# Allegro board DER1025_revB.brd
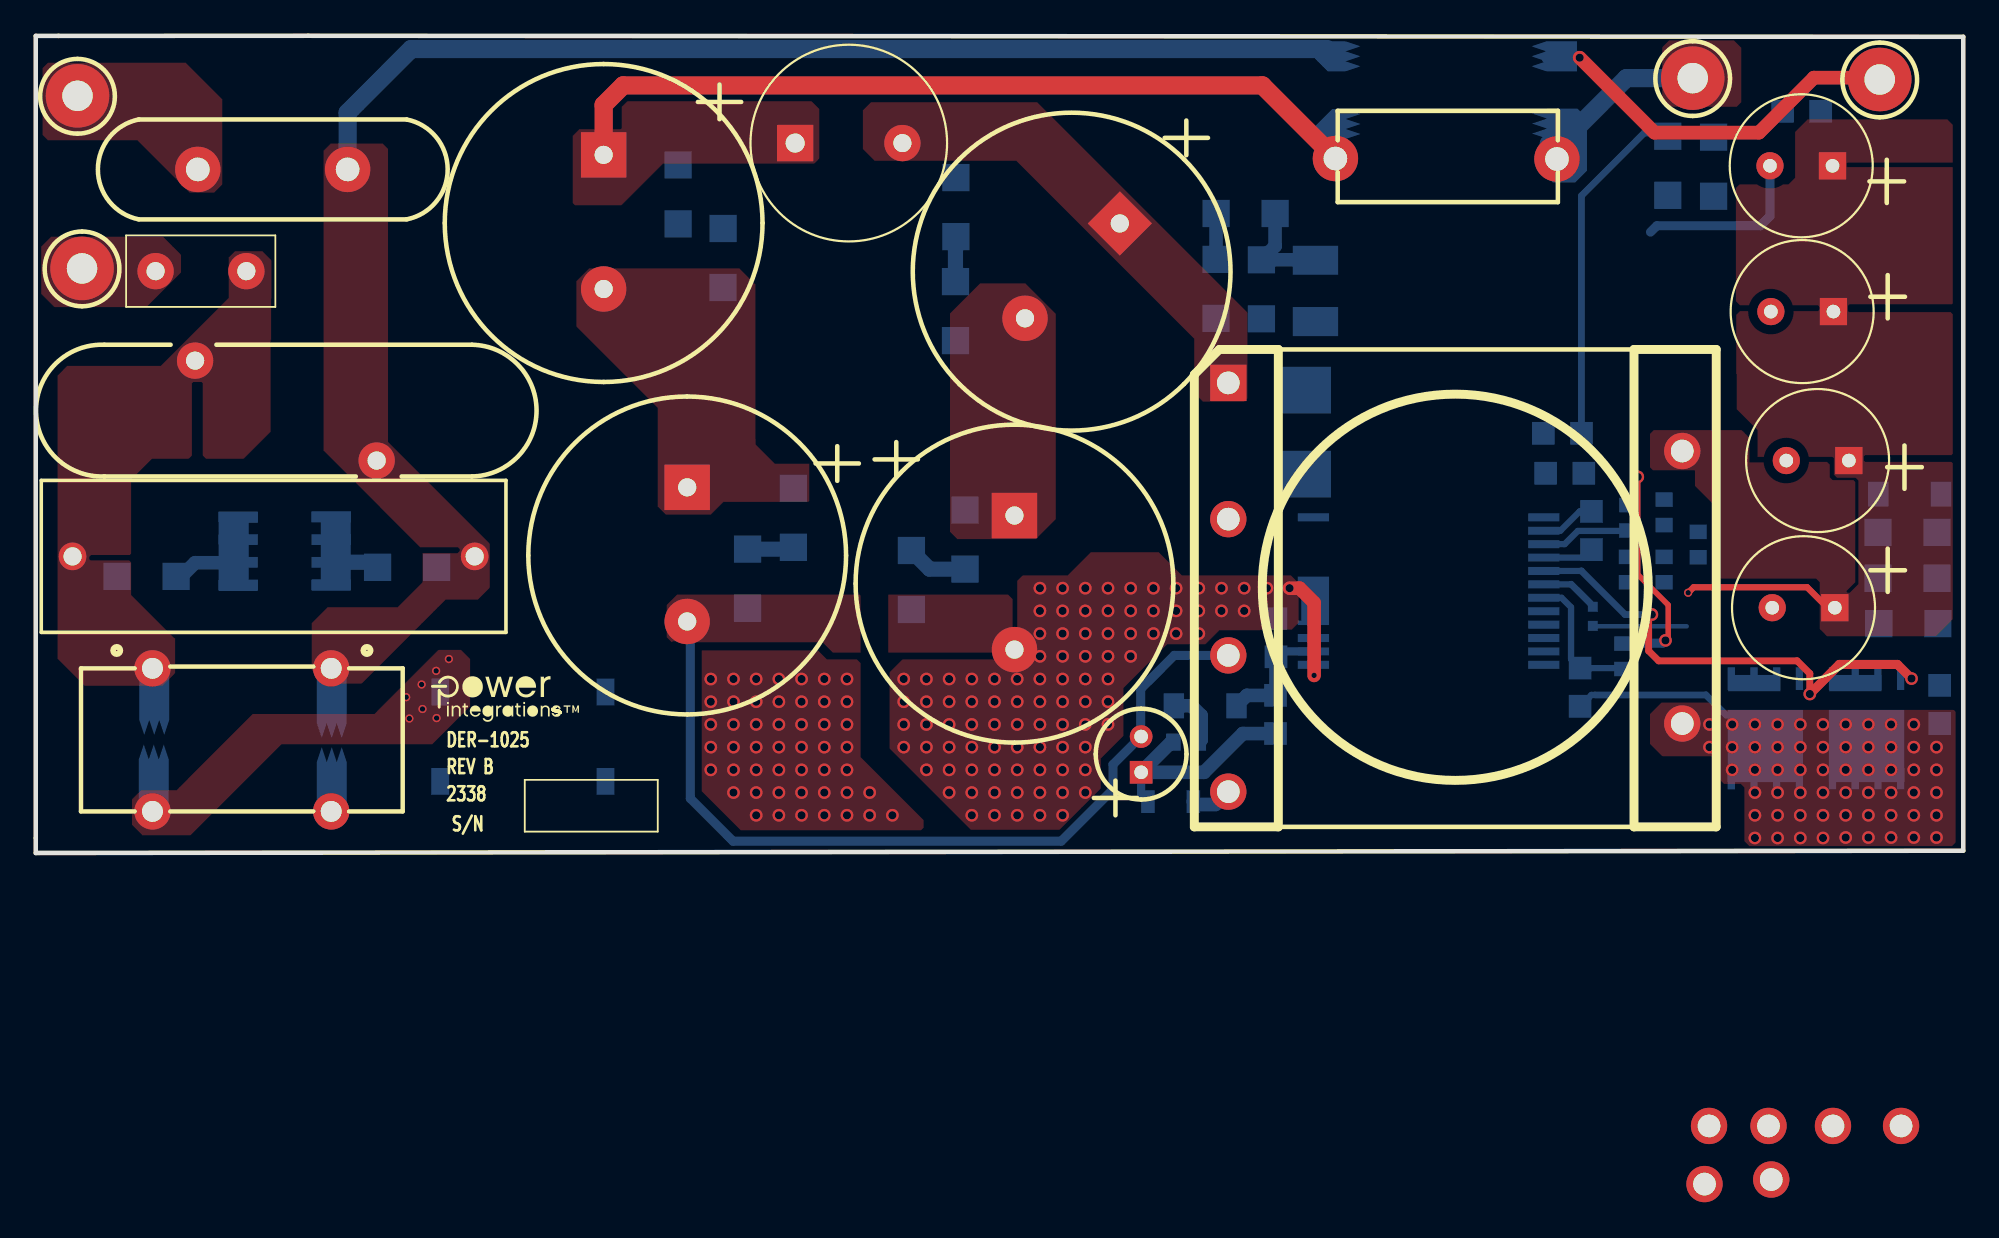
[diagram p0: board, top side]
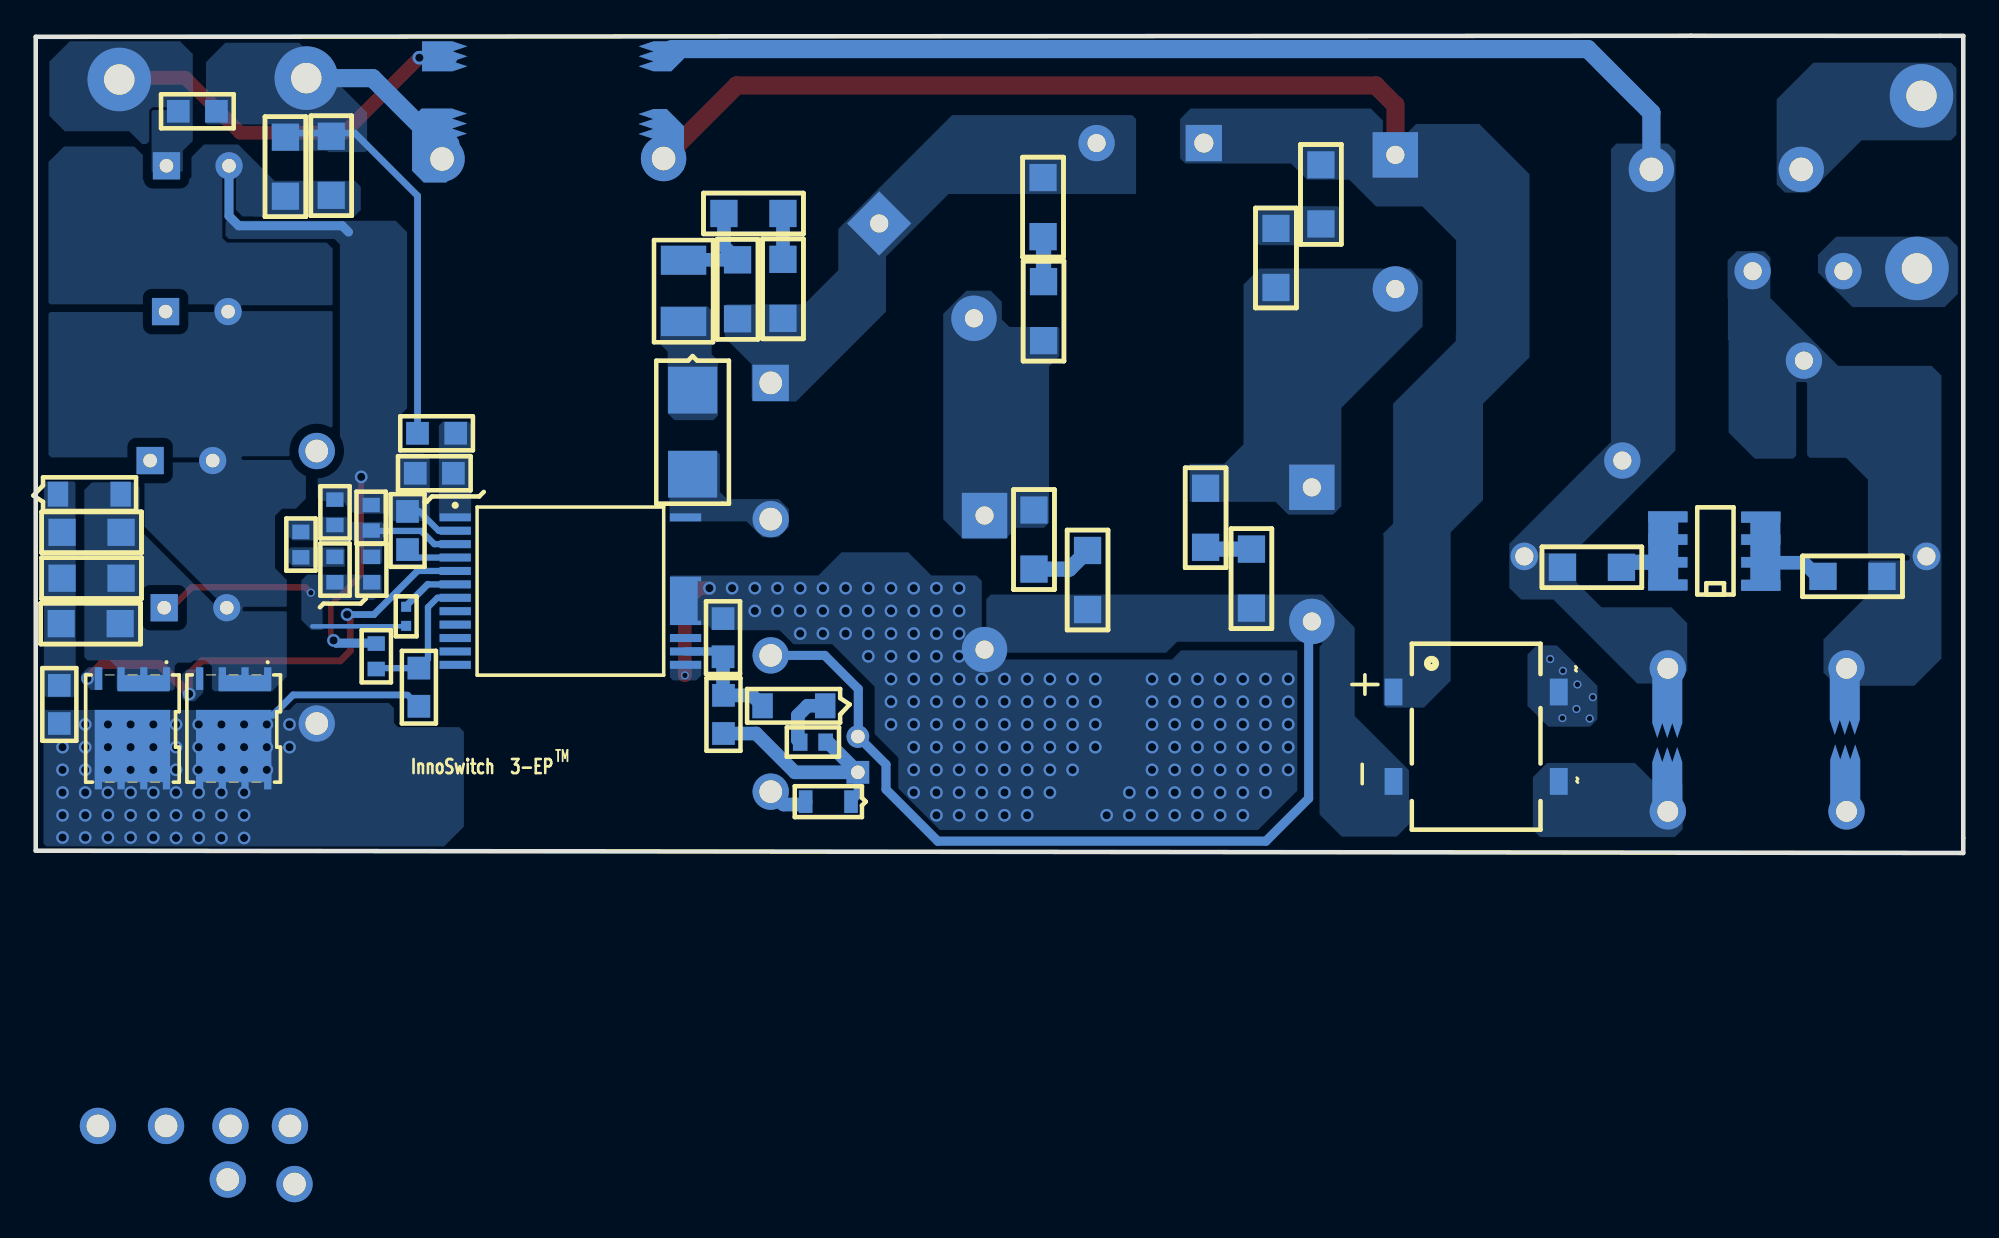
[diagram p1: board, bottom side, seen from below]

Outline 107.85 x 45.7 mm; copper layers: TOP, BOTTOM. Coordinates in mm from the lower left corner of the outline.
Outline path: 0,45.69 0,0 107.85,0.13 107.85,45.64 15.24,45.7 1.27,45.69 0,45.69

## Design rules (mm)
constraint set DEFAULT: min track width 0.203

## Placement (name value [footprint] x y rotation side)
BR1  RTBS60M  [PISMD_RTBS60M]  27.25 6.5 90 bottom
C1  220 uf  [PIPOLCAPCLYD710LS300040]  31.78 39.04 270 top
C2  220 uf  [PIPOLCAPCLYD710LS300040]  36.45 20.45 270 top
C3  220 uf  [PIPOLCAPCLYD710LS300040]  60.66 35.2 225 top
C4  220 uf  [PIPOLCAPCLYD710LS300040]  54.76 18.87 270 top
C5  1 nF  [PISMC1206]  68.58 29.87 90 bottom
C6  22 uF  [PIPOLCAPCLYD5MMD030]  61.85 5.51 90 top
C7  4.7 uF  [PISMC0805]  69.39 10.97 90 bottom
C8  3.3 nF  [PISMC0805]  106.53 7.24 90 bottom
C9  2.2 uF  [PISMC0805]  87.05 19.1 270 bottom
C10  330 pF  [PISMC0603]  88.8 10.29 90 bottom
C11  4.7 uF  [PISMC0805]  86.61 21.23 180 bottom
C12  330 pF  [PISMC0603]  89.08 19.46 270 bottom
C13  10 nF  [PISMC0603]  93.01 16.54 90 bottom
C14  680 uF  [PIPOLCAPCYLD8MMD030]  100.66 13.72 180 top
C15  680 uF  [PIPOLCAPCYLD8MMD030]  101.45 21.95 180 top
C16  680 uF  [PIPOLCAPCYLD8MMD030]  100.58 30.28 180 top
C17  680 uF  [PIPOLCAPCYLD8MMD030]  100.53 38.43 180 top
C18  2.2 uF  [PISMC0805]  99.87 41.48 180 bottom
CX1  220n  [PINPCAPRAD26X8P5X18D040]  13.31 16.59 0 top
CY1  2.2 nF  [PI_NP475X200LS395D040]  73.99 38.96 0 top
D1  S2T-CT  [PISMDO214AA12]  71.09 25.88 270 bottom
D2  BAV21WS-7-F  [PISMSOD323]  62.23 2.87 0 bottom
D3  UFM13PL-TP  [PI_SM_SOD-123_12]  106.6 20.07 180 bottom
F1  5 A  [PI_RST_MICROFUSE]  6.71 32.54 0 top
L  WHT  [PITPKEYSTONE125X125]  2.59 32.69 0 top
L1  2.5 mH  [PI4P18X8MMD046_12_43]  11.53 6.32 0 top
L4  12 uH  [PI_CHOKE_COILCRAFT_RFB1010]  45.49 39.7 0 top
N  BLK  [PITPKEYSTONE125X125]  2.34 42.34 0 top
NOREF  -  []  21.56 9.8 0 top
NOREF#2  -  []  0.05 45.67 0 top
NOREF#3  -  []  107.9 -229.89 0 top
NOREF#4  -  []  0.03 0 90 top
NOREF#5  -  []  -311.94 -305.49 0 top
Q1  SRT15N110L  [PISMPQFN5X6B]  94.87 9.75 0 bottom
Q2  SRT15N110L  [PISMPQFN5X6B]  100.53 9.75 0 bottom
R1  56.2 k  [PISMR1206]  4.55 15.47 0 bottom
R2  56.2 k  [PISMR1206]  19.13 15.98 0 bottom
R3  10 M  [PISMR1206]  35.94 38.48 270 bottom
R4  10 M  [PISMR1206]  38.46 34.92 270 bottom
R5  10 M  [PISMR1206]  42.39 20.4 270 bottom
R6  10 M  [PISMR1206]  39.83 16.99 270 bottom
R7  10 M  [PISMR1206]  51.49 37.77 270 bottom
R8  10 M  [PISMR1206]  51.46 31.95 270 bottom
R9  10 M  [PISMR1206]  51.99 19.18 270 bottom
R10  10 M  [PISMR1206]  49 16.92 270 bottom
R11  560 k  [PISMR1206]  66.04 29.9 90 bottom
R12  560 k  [PISMR1206]  66.04 35.76 0 bottom
R13  20  [PISMR1210]  71.6 33.15 270 bottom
R14  10  [PISMR0603]  63.65 6.2 0 bottom
R15  7.32 k  [PISMR0805]  69.37 6.68 90 bottom
R16  47.0  [PISMR0805]  86.41 8.2 90 bottom
R17  12  [PISMR1206]  106.38 15.37 180 bottom
R18  12  [PISMR1206]  106.43 12.83 180 bottom
R19  12  [PISMR1206]  106.38 17.93 180 bottom
R20  10  [PISMR0402]  87.12 12.7 90 bottom
R21  102 k  [PISMR0603]  89.05 15.14 90 bottom
R22  11.8 k  [PISMR0603]  91.11 18.34 90 bottom
R23  15 k  [PISMR0603]  91.11 15.14 90 bottom
R24  0.013 Ohms  [PISMR1206]  91.31 36.78 90 bottom
R25  0.013 Ohms  [PISMR1206]  93.88 36.73 90 bottom
R32  10  [PISMR0805]  86.49 23.47 180 bottom
RT1  5  [PI_RAD770X220LS330D052]  17.45 38.23 180 top
RTN  BLK  [PITPKEYSTONE125X125]  92.71 43.33 0 top
RV1  820V  [PI_DISC1100X290LS400X220D040]  8.92 27.53 0 top
T1  PQ26/20  [PI_BOBBIN_BPQ26_20_12P_2]  79.43 14.86 0 top
U1  CAP200DG  [PI_IC_SMD_SO8_CAPZERO]  11.33 14.99 90 bottom
U2  INN3699C-H606  [PI_IC_INSOP_24D]  84.38 18.77 180 bottom
VO  RED  [PITPKEYSTONE125X125]  103.17 43.26 0 top
VR1  MMSZ5247BT1G  [PI_SM_SOD-123_12]  63.68 8.23 0 bottom

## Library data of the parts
BR1 = DIODE BRIDGE_+-~~
C1-C4 = CAP POL: alternate symbols: (pi_cap_cly_d710_ls300_040_1000h,pipolcapd710ls3000401600lhoriz)
C5 C7 C9 C11 C12 CY1 = CAP NP
C6 = CAP POL: alternate symbols: (pipolcapclyd5x11mmd030H)
C8 C18 = CAP NP: alternate symbols: (Unisem_RMCF0805UL)
C10 C13 = CAP NP: alternate symbols: (Unisem_RMCF0603UL)
C14-C17 = CAP POL: alternate symbols: (pipolcapcyld8x16mmd030H)
CX1 = CAP NP: alternate symbols: (pinpcaprad26x8p5x18d040H)
D1-D3 = DIODE
F1 = FUSE: alternate symbols: (pirstmicrofusehoz)
L = TESTPOINT: alternate symbols: (TP_5010-14)
L1 = TORRID 4P_12_43a
L4 = INDUCTOR
N RTN VO = TESTPOINT
Q1 Q2 = FET_N_SGD_123_4_5678
R1-R14 R16-R19 R24 R25 R32 = R
R15 = R: alternate symbols: (Unisem_RMCF0805UL)
R20 = R: alternate symbols: (Unisem_RMCF0402UL,pismr0402_1)
R21-R23 = R: alternate symbols: (Unisem_RMCF0603UL)
RT1 = THERMISTOR
RV1 = VARISTOR
T1 = BPQ26/20_12P/GENERIC
U1 = CAPZero
U2 = Inno3EP_P15
VR1 = DIODE_ZENER

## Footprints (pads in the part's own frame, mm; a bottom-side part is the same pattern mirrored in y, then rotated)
PI4P18X8MMD046_12_43
  round 2.032 hole 1.168: 1(-5,4) 2(-5,-4) 3(5,-4) 4(5,4)
PI_BOBBIN_BPQ26_20_12P_2
  rect 2.032x2.032 hole 1.27: 1(-12.7,11.43)
  round 2.032 hole 1.27: 2(13.945,-33.376) 3(-12.7,3.81) 4(-12.7,-3.81) 5(17.678,-33.122) 6(-12.7,-11.43) 7(17.526,-30.124) 8(12.7,-7.62) 9(21.133,-30.124) 10(14.199,-30.124) 11(12.7,7.62) 12(24.943,-30.124)
PI_CHOKE_COILCRAFT_RFB1010
  rect 2.032x2.032 hole 1.067: 1(-3,0)
  round 2.032 hole 1.016: 2(3,0)
PI_DISC1100X290LS400X220D040
  round 2.032 hole 1.016: 1(0,0) 2(10.16,-5.588)
PI_IC_INSOP_24D
  rect 1.75x0.45 smd: 1(0,0) 2(0,-0.75) 3(0,-1.5) 4(0,-2.25) 5(0,-3) 6(0,-3.75) 7(0,-4.5) 8(0,-5.25) 9(0,-6) 10(0,-6.75) 11(0,-7.5) 12(0,-8.25) 13(12.89,-8.25) 14(12.89,-7.5) 15(12.89,-6.75) 24(12.89,0)
  custom 0.438x0.438 smd: 16(12.89,-4.67)
PI_IC_SMD_SO8_CAPZERO
  rect 0.599x2.2 smd: 1(0,0) 2(1.27,0) 3(2.54,0) 4(3.81,0) 5(3.81,5.199) 6(2.54,5.199) 7(1.27,5.199) 8(0,5.199)
PI_NP475X200LS395D040
  round 2.54 hole 1.321: 1(-1.27,-0.127) 2(11.125,-0.152)
PI_RAD770X220LS330D052
  round 2.54 hole 1.321: 1(0,0) 2(8.382,0)
PI_RST_MICROFUSE
  round 2.032 hole 1.016: 1(0,0) 2(5.08,0)
PI_SM_SOD-123_12
  rect 1.143x1.397 smd: 1(0,0) 2(3.505,0)
PINPCAPRAD26X8P5X18D040
  round 1.549 hole 1.016: 1(-11.25,0) 2(11.25,0)
PIPOLCAPCLYD5MMD030
  rect 1.27x1.27 hole 0.762: 1(-1,0)
  round 1.27 hole 0.762: 2(1,0)
PIPOLCAPCLYD710LS300040
  rect 2.54x2.54 hole 1.016: 1(0,0)
  round 2.54 hole 1.016: 2(7.5,0)
PIPOLCAPCYLD8MMD030
  rect 1.524x1.524 hole 0.762: 1(0,0)
  round 1.524 hole 0.762: 2(3.5,0)
PISMC0603
  rect 0.813x0.965 smd: 1(0,0) 2(1.422,0)
PISMC0805
  rect 1.27x1.27 smd: 1(0,0) 2(2.134,0)
PISMC1206
  rect 1.524x1.524 smd: 1(0,0) 2(3.302,0)
PISMD_RTBS60M
  rect 1.5x1 smd: 1(2.5,4.625) 2(-2.5,4.625) 3(2.5,-4.625) 4(-2.5,-4.625)
PISMDO214AA12
  rect 2.616x2.743 smd: 1(0,0) 2(4.699,0)
PISMPQFN5X6B
  rect 0.406x1.27 smd: 1(0,0) 2(1.27,0) 3(2.54,0) 4(3.81,0)
  rect 0.406x1.219 smd: 5(3.81,5.588) 6(2.54,5.588) 7(1.27,5.588) 8(0,5.588)
PISMR0402
  rect 0.559x0.559 smd: 1(0,0) 2(1.067,0)
PISMR0603
  rect 0.813x0.965 smd: 1(0,0) 2(1.422,0)
PISMR0805
  rect 1.27x1.27 smd: 1(0,0) 2(2.134,0)
PISMR1206
  rect 1.524x1.524 smd: 1(0,0) 2(3.302,0)
PISMR1210
  rect 1.626x2.54 smd: 1(0,0) 2(3.429,0)
PISMSOD323
  rect 0.762x1.27 smd: 1(0,0) 2(2.54,0)
PITPKEYSTONE125X125
  round 3.556 hole 1.702: 1(0,0)

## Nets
GND: BR1.2 C2.2 C4.2 C6.2 C7.2 R6.2 R10.2 T1.4 U2.13(VPIN) U2.16
GND SIGNAL: C18.2 CY1.2 R24.2 R25.2 R32.1 RTN.1
NC8: U2.8
NC9: U2.9
NC10: U2.10
NC11: U2.11
NC12: U2.12
RTN: C11.2 R32.2 U2.1
VO: C14.1 C15.1 C16.1 C17.1 C18.1 R20.1 R21.1 R23.1 T1.11 VO.1
N37461: C8.2 D3.1 R17.1 R18.1 R19.1
N37469: C9.1 C10.2 C11.1 C12.1 C14.2 C15.2 C16.2 C17.2 D3.2 Q1.1 Q1.2 Q1.3(S3) Q2.1 Q2.2 Q2.3(S3) R17.2 R18.2 R19.2 R22.2 R24.1 R25.1 U2.2
N38055: C6.1 D2.1 R14.1 R15.1
N38189: C7.1 R15.2 U2.14 VR1.2
N100542: D1.1 R13.2
N100730: C5.2 R12.2 R13.1
N100745: C3.1 C5.1 L4.2 R7.1 R11.1 T1.1
N100844: R11.2 R12.1
N104424: C8.1 Q1.5 Q1.6 Q1.7 Q1.8 Q2.5 Q2.6 Q2.7 Q2.8 R16.1 T1.8
N108780: C12.2 C13.2 R21.2 R22.1 U2.3
N109833: C13.1 R23.2
N12293127: C10.1 R16.2 U2.7
N12298409: D1.2 T1.3 U2.24
N12305547: Q1.4 Q2.4 U2.5
N12325575: C9.2 U2.4
N12352620: C3.2 C4.1 R8.2 R9.1
N12353333: BR1.1 C1.1 CY1.1 L4.1 R3.1
N12359836: R7.2 R8.1
N12360252: R9.2 R10.1
N12374653: R3.2 R4.1
N12374691: C1.2 C2.1 R4.2 R5.1
N12374751: R5.2 R6.1
N12405316: BR1.3 L1.2
N12405324: BR1.4 L1.3
N12405376: CX1.1 F1.2 L1.1 R1.1 RV1.1
N12405380: CX1.2 L1.4 R2.2 RT1.1 RV1.2
N12407233: F1.1 L.1
N12407237: N.1 RT1.2
N12426226: R20.2 U2.6
N12433775: D2.2 T1.6
N12606053: R14.2 VR1.1
N13222962: R1.2 U1.2
N13223037: R2.1 U1.7

Pads without a net: T1 2 5 7 9 10 12; U1 1 3 4 5 6 8; U2 15

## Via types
v1: diameter 0.711, hole 0.457, TOP to BOTTOM, 207 vias
v2: diameter 0.457, hole 0.305, TOP to BOTTOM, 9 vias

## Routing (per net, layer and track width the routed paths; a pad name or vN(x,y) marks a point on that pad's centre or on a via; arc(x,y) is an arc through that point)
GND: length 53.1
  TOP w0.762: v1(70.15,14.81) 70.71,14.81 71.53,14 v2(71.53,9.93)
  BOTTOM w0.457: C6.2 61.84,6.51 61.82,6.5
  BOTTOM w0.508: T1.4 63.7,11.05 61.82,9.17 61.82,6.51 ; 36.63,12.57 36.63,3.05 39.01,0.66 57.38,0.66 60.27,3.56 60.27,4.95 61.82,6.5 61.82,6.51 ; 61.82,6.51 61.85,6.49
  vias: v1(37.77,9.73) v1(37.77,8.46) v1(37.77,7.19) v1(37.77,5.92) v1(37.77,4.65) v1(39.04,9.73) v1(39.04,8.46) v1(39.04,7.19) v1(39.04,5.92) v1(39.04,4.65) v1(39.04,3.38) v1(40.31,9.73) v1(40.31,8.46) v1(40.31,7.19) v1(40.31,5.92) v1(40.31,4.65) v1(40.31,3.38) v1(40.31,2.11) v1(41.58,9.73) v1(41.58,8.46) v1(41.58,7.19) v1(41.58,5.92) v1(41.58,4.65) v1(41.58,3.38) v1(41.58,2.11) v1(42.85,9.73) v1(42.85,8.46) v1(42.85,7.19) v1(42.85,5.92) v1(42.85,4.65) v1(42.85,3.38) v1(42.85,2.11) v1(44.12,9.73) v1(44.12,8.46) v1(44.12,7.19) v1(44.12,5.92) v1(44.12,4.65) v1(44.12,3.38) v1(44.12,2.11) v1(45.39,9.73) v1(45.39,8.46) v1(45.39,7.19) v1(45.39,5.92) v1(45.39,4.65) v1(45.39,3.38) v1(45.39,2.11) v1(46.66,3.38) v1(46.66,2.11) v1(47.93,2.11) v1(48.56,9.73) v1(48.56,8.46) v1(48.56,7.19) v1(48.56,5.92) v1(49.83,9.73) v1(49.83,8.46) v1(49.83,7.19) v1(49.83,5.92) v1(49.83,4.65) v1(51.1,9.73) v1(51.1,8.46) v1(51.1,7.19) v1(51.1,5.92) v1(51.1,4.65) v1(51.1,3.38) v1(52.37,9.73) v1(52.37,8.46) v1(52.37,7.19) v1(52.37,5.92) v1(52.37,4.65) v1(52.37,3.38) v1(52.37,2.11) v1(53.64,9.73) v1(53.64,8.46) v1(53.64,7.19) v1(53.64,5.92) v1(53.64,4.65) v1(53.64,3.38) v1(53.64,2.11) v1(54.91,9.73) v1(54.91,8.46) v1(54.91,7.19) v1(54.91,5.92) v1(54.91,4.65) v1(54.91,3.38) v1(54.91,2.11) v1(56.18,14.81) v1(56.18,13.54) v1(56.18,12.27) v1(56.18,11) v1(56.18,9.73) v1(56.18,8.46) v1(56.18,7.19) v1(56.18,5.92) v1(56.18,4.65) v1(56.18,3.38) v1(56.18,2.11) v1(57.45,14.81) v1(57.45,13.54) v1(57.45,12.27) v1(57.45,11) v1(57.45,9.73) v1(57.45,8.46) v1(57.45,7.19) v1(57.45,5.92) v1(57.45,4.65) v1(57.45,3.38) v1(57.45,2.11) v1(58.72,14.81) v1(58.72,13.54) v1(58.72,12.27) v1(58.72,11) v1(58.72,9.73) v1(58.72,8.46) v1(58.72,7.19) v1(58.72,5.92) v1(58.72,4.65) v1(58.72,3.38) v1(59.99,14.81) v1(59.99,13.54) v1(59.99,12.27) v1(59.99,11) v1(59.99,9.73) v1(59.99,8.46) v1(59.99,7.19) v1(61.26,14.81) v1(61.26,13.54) v1(61.26,12.27) v1(61.26,11) v1(62.53,14.81) v1(62.53,13.54) v1(62.53,12.27) v1(63.8,14.81) v1(63.8,13.54) v1(63.8,12.27) v1(65.07,14.81) v1(65.07,13.54) v1(65.07,12.27) v1(66.34,14.81) v1(66.34,13.54) v1(67.61,14.81) v1(67.61,13.54) v1(68.88,14.81)
GND SIGNAL: length 33
  BOTTOM w0.381: 93.29,40.26 89.99,40.26 86.49,36.75 R32.1
  BOTTOM w1.016: CY1.2 84.73,38.81 84.66,38.73 ; RTN.1 89,43.33 85.32,39.65 84.66,39.65 84.66,38.73 ; 84.66,38.73 84.66,38.28
VO: length 35.6
  TOP w0.35: C14.1 100.25,13.72 99.11,14.86 92.76,14.86 v2(92.46,14.55)
  TOP w0.762: v1(86.39,44.48) 90.58,40.28 96.42,40.28 99.49,43.36 103.05,43.36
  BOTTOM w0.254: 87.12,12.75 87.17,12.7 ; 92.37,12.67 87.2,12.67
  BOTTOM w0.35: R20.1 87.17,12.7 87.2,12.67
  BOTTOM w0.762: 84.63,44.48 v1(86.39,44.48)
N37469: length 25.4
  TOP w0.305: v1(89.64,21.03) 89.64,15.57 91.34,13.87 91.34,12.04 v1(91.19,11.89)
  BOTTOM w0.35: 88.82,11.73 C10.2 ; 86.44,19.1 86.39,19.1 85.31,18.02 U2.2
  BOTTOM w0.381: 87.07,19.1 C9.1 86.44,19.1
  BOTTOM w0.508: v1(91.19,11.89) 91.03,11.73 88.82,11.73 ; 90.35,34.72 90.7,35.08 96.49,35.08 97.03,35.62 C17.2
N38055: length 12.7
  BOTTOM w0.457: C6.1 61.85,3.25 D2.1
  BOTTOM w0.762: R15.1 67.54,6.68 65.37,4.51 C6.1 63.53,6.2 R14.1
N38189: length 6.8
  BOTTOM w0.457: U2.14 69.69,11.27 C7.1
  BOTTOM w0.762: VR1.2 67.77,8.81 R15.2 69.39,8.84 C7.1
N100730: length 5.9
  BOTTOM w0.762: R12.2 69.34,33.93 C5.2 71.58,33.17 R13.1
N100844: length 2.6
  BOTTOM w0.762: R12.1 R11.2
N104424: length 8.9
  BOTTOM w0.35: R16.1 87.05,8.84 87.25,8.84
  BOTTOM w0.381: 94.59,7.7 93.45,8.84 87.25,8.84
  vias: v1(93.65,7.19) v1(93.65,5.92) v1(94.92,7.19) v1(94.92,5.92) v1(94.92,4.65) v1(96.19,7.19) v1(96.19,5.92) v1(96.19,4.65) v1(96.19,3.38) v1(96.19,2.11) v1(96.19,0.84) v1(97.46,7.19) v1(97.46,5.92) v1(97.46,4.65) v1(97.46,3.38) v1(97.46,2.11) v1(97.46,0.84) v1(98.73,7.19) v1(98.73,5.92) v1(98.73,4.65) v1(98.73,3.38) v1(98.73,2.11) v1(98.73,0.84) v1(100,7.19) v1(100,5.92) v1(100,4.65) v1(100,3.38) v1(100,2.11) v1(100,0.84) v1(101.27,7.19) v1(101.27,5.92) v1(101.27,4.65) v1(101.27,3.38) v1(101.27,2.11) v1(101.27,0.86) v1(102.54,7.19) v1(102.54,5.92) v1(102.54,4.65) v1(102.54,3.38) v1(102.54,2.11) v1(102.54,0.86) v1(103.81,7.19) v1(103.81,5.92) v1(103.81,4.65) v1(103.81,3.38) v1(103.81,2.11) v1(103.81,0.86) v1(105.08,7.19) v1(105.08,5.92) v1(105.08,4.65) v1(105.08,3.38) v1(105.08,2.11) v1(105.08,0.86) v1(106.35,5.92) v1(106.35,4.65) v1(106.35,3.38) v1(106.35,2.11) v1(106.35,0.86)
N108780: length 5
  BOTTOM w0.35: C12.2 89.05,18.01 86.28,18.01 85.55,17.27 U2.3
N12293127: length 7.8
  BOTTOM w0.35: C10.1 88.75,10.34 R16.2 85.9,10.85 85.9,13.74 85.37,14.27 U2.7
N12298409: length 0.4
  BOTTOM w0.381: 71.5,21.16 71.12,21.16 D1.2 ; 66.77,18.77 66.78,18.78
N12305547: length 26.6
  TOP w0.381: v1(99.26,8.89) 99.26,10.03 98.55,10.74 90.81,10.74 90.25,11.3 90.25,13.16 v1(90.42,13.34)
  TOP w0.508: v1(104.95,9.75) 104.17,10.54 100.91,10.54 v1(99.26,8.89)
  BOTTOM w0.35: U2.5 86.47,15.77 86.48,15.78
  BOTTOM w0.381: 86.48,15.78 88.93,13.34 v1(90.42,13.34)
N12325575: length 2.9
  BOTTOM w0.35: C9.2 86.6,16.52 U2.4
  BOTTOM w0.381: 87.07,16.97 C9.2
N12353333: length 45.9
  TOP w1.016: CY1.1 68.63,42.93 32.87,42.93 31.78,41.83 C1.1
N12359836: length 2.5
  BOTTOM w0.85: R7.2 51.46,34.44 R8.1
N12360252: length 3.4
  BOTTOM w0.85: R9.2 50.01,15.88 49,16.89 R10.1
N12374751: length 2.6
  BOTTOM w0.85: R5.2 42.29,16.99 R6.1
N12405316:
  vias: v2(20.73,8.71) v2(20.9,7.52) v2(21.59,9.42) v2(21.64,8.05) v2(22.4,10.19) v2(22.43,7.54) v2(23.11,10.85)
N12405380: length 59.5
  BOTTOM w1.016: RT1.1 17.45,41.4 21.01,44.96 72.26,44.96
N12426226: length 3.3
  BOTTOM w0.35: 85.91,15.03 85.9,15.02 U2.6 ; 87.12,13.82 R20.2
  BOTTOM w0.381: 85.91,15.03 87.12,13.82
N12433775: length 2.3
  BOTTOM w0.762: D2.2 64.93,2.71 66.01,2.71 66.73,3.43
N12606053: length 3.3
  BOTTOM w0.762: R14.2 65.21,6.33 65.21,7.69 64.67,8.23 VR1.1
N13222962: length 3.8
  BOTTOM w0.762: U1.2 11.3,16.23 8.92,16.23 8.15,15.47 R1.2
N13223037: length 2.7
  BOTTOM w0.85: U1.7 18.85,16.26 R2.1

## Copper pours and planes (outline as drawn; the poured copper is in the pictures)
GND on TOP: 55.22,15.52 57.76,15.52 57.76,15.54 59.03,16.81 62.84,16.81 64.14,15.52 70.23,15.52 70.66,15.09 70.66,12.88 70.28,12.5 68.88,12.5 68.88,12.47 68.5,12.47 68.49,12.46 66.23,12.46 65.44,11.67 63.31,11.67 60.86,9.22 60.86,6.55 59.59,5.28 59.59,3.61 57.28,1.3 52.32,1.3 47.78,5.84 47.78,10.11 48.49,10.82 53.62,10.82 53.72,10.92 53.72,11.07 53.59,11.2 47.7,11.2 47.7,14.43 47.73,14.45 54.41,14.45 54.66,14.2 54.66,12.27 54.74,12.19 54.86,12.19 54.91,12.24 54.91,15.21
GND on TOP: 43.76,11.33 44.27,10.82 45.95,10.82 46.15,10.62 46.15,5.36 49.68,1.83 49.68,1.42 49.53,1.27 39.45,1.27 37.26,3.45 37.26,11.33
GND on TOP: 46.15,11.2 44.6,11.2 44.02,11.79 36.8,11.79 36.75,11.84 35.64,11.84 35.59,11.79 35.31,12.06 35.31,13.87 35.89,14.45 46.1,14.45 46.15,14.4
GND on BOTTOM: 55.22,15.52 57.73,15.52 59.03,16.81 62.76,16.81 64.06,15.52 72.34,15.52 72.34,12.8 72.29,12.75 70.26,12.75 69.98,12.47 68.5,12.47 68.49,12.46 66.23,12.46 65.44,11.67 63.28,11.67 60.91,9.3 60.91,6.65 59.59,5.33 59.59,3.61 57.26,1.28 39.46,1.28 37.26,3.48 37.26,11.33 43.76,11.33 44.27,10.82 53.62,10.82 53.72,10.92 53.72,11.07 53.59,11.2 44.6,11.2 43.99,11.81 35.94,11.81 35.86,11.73 35.86,11.68 36.02,11.53 36.02,2.16 34.77,0.91 31.7,0.91 31.01,1.6 31.01,4.62 34.05,7.66 34.05,12.61 35.26,13.82 35.26,13.84 35.86,14.45 54.41,14.45 54.66,14.2 54.66,12.27 54.74,12.19 54.86,12.19 54.91,12.24 54.91,15.21
GND on BOTTOM: 70.61,10.74 72.29,10.74 72.36,10.67 72.36,9.83 72.19,9.65 70.89,9.65 70.61,9.93
GND SIGNAL on BOTTOM (solid shape): 86.79,41.1 86.79,38.15 86.13,37.49 84.89,37.49 84.53,37.85 84.53,39.96 83.72,40.23 84.56,40.51 83.72,40.79 84.56,41.07 83.72,41.35 84.56,41.63 86.26,41.63
GND SIGNAL on TOP: 95.02,45.44 95.43,45.03 95.43,41.99 95.17,41.73 91.41,41.73 91.01,42.14 91.01,45.06 91.39,45.44
GND SIGNAL on BOTTOM: 98.25,40.74 98.32,40.82 98.32,44.22 97.23,45.31 93.12,45.31 91.92,44.12 91.92,44.02 89.31,41.4 89.31,39.29 89.41,39.19 91.47,39.19 91.54,39.27 94.11,39.27 94.11,40.13 94.72,40.74
RTN on BOTTOM: 85.29,18.59 85.29,23.9 85.06,24.13 83.67,24.13 83.49,23.95 83.49,18.57 83.52,18.54 85.24,18.54
VO on BOTTOM (solid shape): 86.23,43.71 84.53,43.71 83.69,43.99 84.53,44.27 83.69,44.55 84.53,44.83 83.69,45.11 84.53,45.39 86.23,45.39
VO on TOP: outline of 86 points within 90.32,12.12 107.26,41.02
VO on BOTTOM: 99.77,45.39 105.94,45.39 107.09,44.25 107.09,41.22 106.22,40.36 102.62,40.36 101.9,39.65 101.65,39.65 101.5,39.8 101.5,41.53 101.32,41.71 100.53,41.71 100.51,41.68 100.51,41.58 100.53,41.55 101.27,41.55 101.37,41.45 101.37,38.1 99.67,38.1 99.62,38.15 99.62,39.27 99.06,39.83 99.06,44.68
VO on BOTTOM: 88.57,15.57 92.66,15.57 92.99,15.24 92.99,13.03 92.43,12.47 91.8,12.47 91.8,13.72 91.36,14.15 88.85,14.15 88.49,14.5 88.49,15.49
N37461 on BOTTOM: 107.39,8.86 107.24,8.71 105.77,8.71 105.61,8.86 105.61,18.24 105.63,18.25 105.63,20.69 105.71,20.78 107.31,20.78 107.39,20.7
N37469 on BOTTOM (solid shape): 97.61,9.04 94.69,9.04 94.69,9.96 97.61,9.96
N37469 on BOTTOM (solid shape): 103.28,9.04 100.36,9.04 100.36,9.96 103.28,9.96
N37469 on BOTTOM: outline of 107 points within 89.66,9.04 107.14,39.62
N37469 on BOTTOM: 86.08,18.47 87.71,18.47 88.21,18.97 90.02,18.97 90.55,19.51 90.55,19.56 90.68,19.68 91.9,19.68 92.08,19.86 92.08,21.08 90.83,22.33 90.83,34.04 91.14,34.34 97.05,34.34 97.23,34.52 97.23,35.28 97.16,35.36 87.71,35.36 87.07,34.72 87.07,24.87 87.48,24.46 87.48,22.71 87.12,22.35 86.16,22.35 85.8,22 85.8,18.75
N100542 on BOTTOM: 70.28,30.58 72.85,30.58 72.91,30.52 72.91,28.46 72.49,28.04 72.49,24.59 72.11,24.21 69.93,24.21 69.67,24.46 69.67,27.53 70.03,27.89 70.03,30.33
N100745 on TOP: 67.79,30.23 67.79,25.43 67.61,25.25 65.3,25.25 64.82,25.73 64.82,28.75 54.86,38.71 46.94,38.71 46.28,39.37 46.28,41.53 46.71,41.96 46.71,41.99 56.03,41.99
N100745 on BOTTOM: 56.58,41.26 62.94,34.9 62.94,32.59 64.85,30.68 69.19,30.68 69.29,30.58 69.29,28.83 67.79,27.33 67.79,25.43 67.61,25.25 65.3,25.25 60.27,30.28 60.27,33.35 56.77,36.86 46.28,36.86 46.28,41.05 46.49,41.26
N104424 on BOTTOM (solid shape): 98.88,3.96 94.67,3.96 94.67,8 98.88,8
N104424 on BOTTOM (solid shape): 104.55,3.96 100.33,3.96 100.33,8 104.55,8
N104424 on TOP: 93.65,8.41 94.06,8 107.31,8 107.42,7.9 107.42,0.58 107.21,0.38 95.89,0.38 95.61,0.66 95.61,3.66 95.4,3.86 94.46,3.86 94.21,4.11 94.21,5.03 93.83,5.41 91.01,5.41 90.32,6.1 90.32,7.77 90.96,8.41
N104424 on BOTTOM: 107.31,8 107.42,7.9 107.42,0.53 107.25,0.37 85,0.37 83.9,1.47 83.9,6.78 84.15,7.04 87.58,7.04 87.81,7.26 87.81,8.1 88.09,8.38 93.27,8.38 93.65,8
N108780 on BOTTOM: 90.22,18.52 90.51,18.81 90.53,18.8 93.42,18.8 93.7,18.52 93.7,17.7 93.47,17.48 90.09,17.48 89.66,17.04 89.66,16.23 89.59,16.15 88.57,16.15 88.47,16.26 88.47,17.55 88.11,17.91 88.11,18.14 88.49,18.52
N109833 on BOTTOM: 93.57,17.09 90.65,17.09 90.55,16.99 90.55,16 93.45,16 93.68,16.23 93.68,16.99
N12298409 on BOTTOM: 72.39,18.54 68.07,18.54 67.18,17.65 66.29,17.65 65.71,18.24 65.71,19.23 66.27,19.79 69.16,19.79 69.57,20.19 69.57,22.3 69.72,22.45 72.39,22.45
N12305547 on BOTTOM: 104.14,10.39 104.9,10.39 105.31,9.98 105.31,9.65 104.78,9.12 104.09,9.12 104.09,10.34
N12305547 on BOTTOM: 98.48,10.41 99.24,10.41 99.67,9.98 99.67,8.66 99.49,8.48 98.96,8.48 98.48,8.97
N12352620 on TOP: 57.07,30.15 57.07,18.67 55.96,17.55 51.56,17.55 51.16,17.96 51.16,30.18 52.83,31.85 55.37,31.85
N12352620 on BOTTOM: 57.07,30.15 57.07,18.67 55.96,17.55 53.52,17.55 53.52,17.63 52.96,18.19 51.43,18.19 51.16,18.47 51.16,27.2 50.57,27.79 50.57,29.34 50.65,29.41 53.37,29.41 53.8,29.84 53.8,30.84 54.41,31.45 55.78,31.45
N12353333 on BOTTOM (solid shape): 74.12,41.33 73.28,41.05 74.12,40.77 73.28,40.49 74.12,40.21 73.28,39.93 73.28,38.28 72.87,37.87 71.96,37.87 71.58,38.25 71.58,40.64 72.54,41.61 73.28,41.61
N12353333 on TOP: 35.1,38.56 32.77,36.22 30.18,36.22 30.05,36.35 30.05,40.11 30.42,40.47 32.73,40.47 32.79,40.54 32.79,41.73 33.1,42.04 43.41,42.04 43.84,41.61 43.84,38.84 43.56,38.56
N12353333 on BOTTOM: 26.87,19.74 26.87,25.12 24.27,27.72 24.27,37.96 27.08,40.77 30.61,40.77 31.04,40.34 31.04,38.48 31.29,38.23 32.31,38.23 32.47,38.39 32.47,40.96 33.15,41.63 43.23,41.63 43.81,41.05 43.81,38.84 43.54,38.56 37.62,38.56 36.72,37.66 34.35,37.66 32.85,36.16 30.26,36.16 28.37,34.26 28.37,29.01 28.4,28.98 28.4,28.63 31.9,25.12 31.9,18.41 32.49,17.83 32.44,17.78 32.44,8.31 32.26,8.13 30.18,8.13 28.68,9.63 28.68,17.93
N12374653 on BOTTOM: 35,36.17 39.29,36.17 39.65,35.81 39.65,34.26 39.37,33.99 35.05,33.99 34.8,34.24 34.8,35.97
N12374691 on TOP, BOTTOM: 40.27,23.14 40.28,23.13 40.28,22.84 41.35,21.77 43.28,21.77 43.28,19.68 43.23,19.63 38.48,19.63 37.77,18.92 35.26,18.92 34.8,19.38 34.8,24.89 30.25,29.44 30.25,31.98 30.96,32.69 39.37,32.69 40.27,31.79
N12405316 on BOTTOM (solid shape): 7.44,5.23 7.44,2.18 5.77,2.18 5.77,5.23 6.05,6.07 6.32,5.23 6.6,6.07 6.88,5.23 7.16,6.07
N12405316 on TOP: 13.75,6.08 22.19,6.08 24.31,8.2 24.31,10.85 23.8,11.35 22.53,11.35 18.95,7.77 12.14,7.77 7.87,3.51 5.89,3.51 5.38,3 5.38,1.57 5.99,0.97 6.02,0.99 8.66,0.99
N12405316 on BOTTOM: 22.73,11.61 23.88,11.61 24.38,11.1 24.38,8.23 23.22,7.06 20.88,7.06 20.47,7.47 20.47,9.35
N12405324 on BOTTOM (solid shape): 17.4,5.08 17.4,2.06 15.72,2.06 15.72,5.08 16,5.92 16.28,5.08 16.56,5.92 16.84,5.08 17.12,5.92
N12405324 on BOTTOM: 18.36,5.03 17.17,3.84 15.67,3.84 15.7,3.81 15.7,1.32 16.13,0.89 23.67,0.89 24.08,1.3 24.08,4.24 23.29,5.03
N12405376 on BOTTOM (solid shape): 7.47,7.44 7.19,6.6 6.91,7.44 6.63,6.6 6.35,7.44 6.07,6.6 5.79,7.44 5.79,10.26 7.47,10.26
N12405376 on TOP: 11.15,33.66 12.67,33.66 13.18,33.15 13.18,31.01 13.17,31 13.17,28.71 13.14,28.69 13.14,23.56 11.63,22.05 9.52,22.05 9.35,22.23 9.35,26.26 9.27,26.34 8.81,26.34 8.74,26.26 8.74,22.23 8.56,22.05 6.5,22.05 5.33,20.88 5.33,16.74 5.26,16.66 3.1,16.66 3,16.56 3,16.43 3.07,16.36 5.23,16.36 5.33,16.26 5.33,14.43 7.75,12.01 7.8,12.01 7.8,10.06 7.09,9.35 2.74,9.35 1.22,10.87 1.22,26.7 1.77,27.24 7,27.24 10.79,31.04 10.79,33.3
N12405376 on BOTTOM: 11.15,33.66 12.67,33.66 13.18,33.15 13.18,31.01 13.17,31 13.17,28.71 13.13,28.68 13.13,23.52 11.66,22.05 9.52,22.05 9.35,22.23 9.35,26.29 9.3,26.34 8.81,26.34 8.74,26.26 8.74,22.25 8.59,22.1 6.55,22.1 5.33,20.88 5.33,16.74 5.26,16.66 3.1,16.66 3,16.56 3,16.43 3.07,16.36 5.23,16.36 5.33,16.26 5.33,14.43 7.77,11.99 7.82,11.99 7.82,10.08 7.09,9.35 2.74,9.35 1.22,10.87 1.22,26.7 1.77,27.24 7,27.24 10.79,31.04 10.79,33.3
N12405380 on BOTTOM (solid shape): 17.4,7.26 17.12,6.43 16.84,7.26 16.56,6.43 16.28,7.26 16,6.43 15.72,7.26 15.72,10.36 17.4,10.36
N12405380 on BOTTOM (solid shape): 74.12,45.11 73.28,44.83 74.12,44.55 73.28,44.27 74.12,43.99 73.28,43.71 72.29,43.71 71.58,44.42 71.58,45.39 73.28,45.39
N12405380 on TOP: 16.51,39.67 19.41,39.67 19.71,39.37 19.71,22.99 25.4,17.3 25.4,14.83 24.74,14.17 22.94,14.17 18.24,9.47 16.21,9.47 15.44,10.24 15.44,12.85 16.33,13.74 20.24,13.74 21.64,15.14 21.64,16.76 23.6,16.76 23.72,16.89 23.72,16.99 23.62,17.09 21.51,17.09 16.1,22.5 16.1,39.27
N12405380 on BOTTOM: 16.51,39.67 19.41,39.67 19.71,39.37 19.71,22.99 25.4,17.3 25.4,14.83 24.74,14.17 22.94,14.17 18.24,9.47 16.15,9.47 15.44,10.19 15.44,12.85 16.33,13.74 20.24,13.74 21.64,15.14 21.64,16.76 23.6,16.76 23.72,16.89 23.72,16.99 23.62,17.09 21.51,17.09 16.1,22.5 16.1,39.27
N12407233 on TOP, BOTTOM: 0.86,34.47 7.11,34.47 8.13,33.45 8.13,32.46 6.2,30.53 1.04,30.53 0.3,31.27 0.3,33.91
N12407237 on TOP, BOTTOM: 0.69,44.2 8.38,44.2 10.44,42.14 10.44,37.39 9.98,36.93 8.61,36.93 5.69,39.85 0.69,39.85 0.38,40.16 0.38,43.89
N13222962 on BOTTOM (solid shape): 12.42,18.47 11.91,18.47 11.91,15.27 12.42,15.27 12.42,14.66 10.24,14.66 10.24,19.08 12.42,19.08
N13223037 on BOTTOM (solid shape): 17.63,14.68 15.44,14.68 15.44,15.29 15.95,15.29 15.95,18.49 15.44,18.49 15.44,19.1 17.63,19.1

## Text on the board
Ref Des/Silkscreen Bottom: TM | InnoSwitch  3-EP
Ref Des/Silkscreen Top: DER-1025 | REV B | 2338 | S/N
User.6: 11.  TRACE SPACE +/- 0.003" | 14. VIAS FILLED | 13. 2 LAYERS BOARD: TOP,BOTTOM. | PLEASE DELETE THESE PINS
User.10: FIGURE | FINISHED_SIZE | 12.0 | 17.99 | 30.0 | 40.0 | 42.0 | 46.0 | 50.0 | 52.01 | 67.01 | DRILL CHART: TOP to BOTTOM | ALL UNITS ARE IN MILS | TOLERANCE_DRILL | +0.0/-0.0 | +2.99/-2.99 | PLATED | QTY | 9 | 207 | 10 | 14 | 1 | 4 | 12
